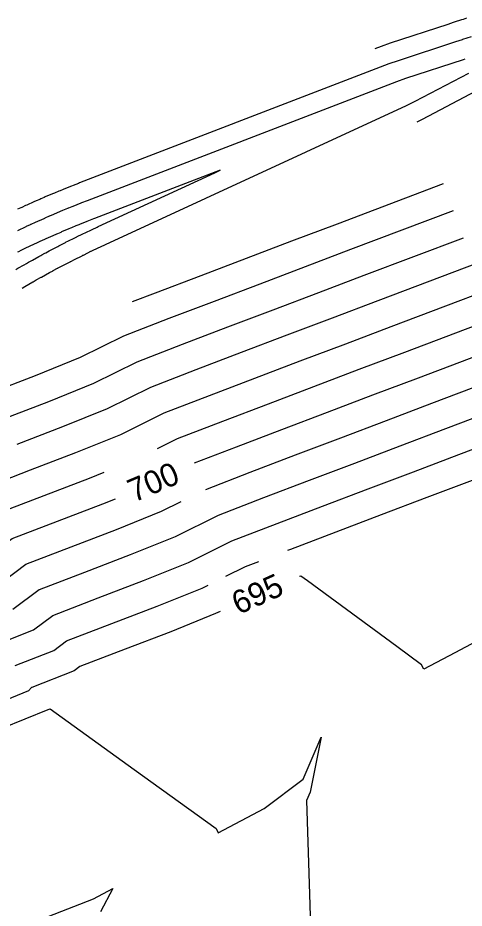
# Model space of a CAD drawing. Extents: x 1487507 to 1489130, y 497211 to 499439.
# Drawn here: x 1488002.7 to 1488049, y 498507 to 498599.3 of the extents above; entities that cross this region are included whole.
import ezdxf

# ---------------------------------------------------------------- set-up
doc = ezdxf.new("R2010")
doc.units = 0
for name, color, linetype in [('Prop CMT Ditch DDE', 7, 'Continuous'), ('Prop Drainage Ditch Flow Line', 7, 'Continuous'), ('Prop Drainage Structure Pipe Outlet Channel Detail CELL', 7, 'Continuous')]:
    doc.layers.add(name, color=color, linetype=linetype)

msp = doc.modelspace()

# ---------------------------------------------------------------- linework, layer by layer
at = {"layer": 'Prop CMT Ditch DDE'}
for points in [[(1488039.747, 498596.07), (1488040.392, 498596.318), (1488041.336, 498596.654), (1488047.303, 498598.602), (1488047.879, 498598.79), (1488047.981, 498598.823), (1488048.73, 498599.075), (1488048.888, 498599.128), (1488049.261, 498599.256)], [(1488049.698, 498597.299), (1488048.812, 498597), (1488048.773, 498596.987), (1488048.745, 498596.977), (1488048.081, 498596.76), (1488042.114, 498594.811), (1488041.17, 498594.476), (1488009.111, 498582.152), (1488008.992, 498582.105), (1488008.457, 498581.897), (1488008.267, 498581.821), (1488007.486, 498581.509), (1488007.402, 498581.475), (1488007.101, 498581.352), (1488006.97, 498581.298), (1488006.519, 498581.111), (1488006.294, 498581.016), (1488005.556, 498580.704), (1488005.445, 498580.656), (1488005.106, 498580.51), (1488004.981, 498580.455), (1488004.596, 498580.286), (1488004.365, 498580.183), (1488003.64, 498579.859), (1488003.517, 498579.803), (1488003.128, 498579.626), (1488003.024, 498579.578), (1488002.689, 498579.423)], [(1488049.04, 498594.977), (1488048.859, 498594.917), (1488042.892, 498592.969), (1488041.949, 498592.633), (1488009.889, 498580.309), (1488009.321, 498580.088), (1488009.248, 498580.06), (1488008.393, 498579.719), (1488008.295, 498579.68), (1488007.954, 498579.541), (1488007.917, 498579.526), (1488007.862, 498579.503), (1488007.346, 498579.29), (1488006.476, 498578.923), (1488006.401, 498578.891), (1488005.993, 498578.715), (1488005.96, 498578.701), (1488005.493, 498578.497), (1488005.459, 498578.482), (1488005.397, 498578.454), (1488004.522, 498578.064), (1488004.045, 498577.847), (1488004.019, 498577.835), (1488003.998, 498577.825), (1488003.588, 498577.636), (1488003.547, 498577.617), (1488002.658, 498577.199)], [(1488003.162, 498571.258), (1488003.448, 498571.427), (1488004.271, 498571.903), (1488004.29, 498571.914), (1488004.298, 498571.919), (1488004.623, 498572.104), (1488005.119, 498572.383), (1488005.137, 498572.393), (1488005.168, 498572.41), (1488005.99, 498572.864), (1488006.365, 498573.068), (1488006.386, 498573.079), (1488006.82, 498573.312), (1488006.847, 498573.327), (1488006.898, 498573.354), (1488007.709, 498573.781), (1488008.134, 498574.001), (1488008.17, 498574.019), (1488008.201, 498574.035), (1488008.576, 498574.226), (1488009.365, 498574.622), (1488009.447, 498574.663), (1488009.498, 498574.688), (1488009.974, 498574.922), (1488010.286, 498575.073), (1488010.324, 498575.091), (1488011.101, 498575.462), (1488011.204, 498575.511), (1488011.275, 498575.544), (1488011.798, 498575.788), (1488042.988, 498590.173), (1488043.886, 498590.615), (1488049.443, 498593.533)], [(1488044.08, 498588.486), (1488044.664, 498588.773), (1488050.221, 498591.691)], [(1488087.147, 498587.769), (1488040.009, 498569.944), (1488035.296, 498568.161), (1488030.584, 498566.375), (1488025.873, 498564.587), (1488021.163, 498562.797), (1488016.465, 498560.986), (1488011.983, 498558.766), (1488007.322, 498556.883), (1488002.617, 498555.084)], [(1488017.17, 498554.642), (1488019.272, 498555.683), (1488023.971, 498557.494), (1488028.68, 498559.284), (1488033.391, 498561.072), (1488038.103, 498562.858), (1488042.817, 498564.641), (1488089.955, 498582.465), (1488091.211, 498582.934), (1488094.526, 498584.179), (1488095.693, 498584.618), (1488099.077, 498585.901), (1488100.17, 498586.256)], [(1487999.317, 498550.632), (1488004.02, 498552.433), (1488008.725, 498554.232), (1488013.386, 498556.114), (1488017.868, 498558.334), (1488022.567, 498560.146), (1488027.277, 498561.936), (1488031.988, 498563.724), (1488036.7, 498565.509), (1488041.413, 498567.293), (1488088.551, 498585.117)], [(1488046.785, 498582.054), (1488035.798, 498577.9), (1488031.085, 498576.116), (1488026.373, 498574.33), (1488021.662, 498572.542), (1488016.952, 498570.752), (1488014.566, 498569.832)], [(1488022.193, 498550.423), (1488026.778, 498552.191), (1488031.488, 498553.981), (1488036.199, 498555.769), (1488040.911, 498557.554), (1488045.624, 498559.338), (1488092.762, 498577.162), (1488093.195, 498577.323), (1488097.349, 498578.884), (1488097.695, 498579.014), (1488097.794, 498579.052)], [(1488001.213, 498557.736), (1488005.918, 498559.535), (1488010.579, 498561.418), (1488015.061, 498563.638), (1488019.76, 498565.449), (1488024.469, 498567.239), (1488029.18, 498569.027), (1488033.892, 498570.813), (1488038.605, 498572.596), (1488048.891, 498576.485)], [(1488094.166, 498574.51), (1488047.028, 498556.686), (1488042.314, 498554.903), (1488037.602, 498553.117), (1488032.891, 498551.329), (1488028.182, 498549.539), (1488023.483, 498547.727), (1488019.001, 498545.507), (1488014.34, 498543.625), (1488009.635, 498541.826), (1488004.931, 498540.025), (1488002.199, 498537.977)], [(1488000.749, 498534.455), (1488004.32, 498535.863), (1488006.335, 498537.373), (1488011.039, 498539.174), (1488015.744, 498540.973), (1488020.405, 498542.856), (1488024.887, 498545.076), (1488029.585, 498546.887), (1488034.295, 498548.677), (1488039.006, 498550.465), (1488043.718, 498552.251), (1488048.431, 498554.034), (1488074.272, 498563.806)], [(1487940.538, 498514.989), (1487953.072, 498520.432), (1487957.673, 498522.429), (1487962.274, 498524.424), (1487966.876, 498526.418), (1487971.478, 498528.41), (1487972.399, 498528.808), (1487973.558, 498529.31), (1487975.712, 498531.1), (1487977.261, 498531.763), (1487979.821, 498534.024), (1487981.476, 498534.703), (1487983.912, 498536.984), (1487985.699, 498537.574), (1487988.117, 498539.726), (1487989.914, 498540.428), (1487991.762, 498541.175), (1487993.944, 498543.574), (1487993.948, 498543.575), (1487995.835, 498544.319), (1488000.72, 498547.98), (1488005.424, 498549.781), (1488010.129, 498551.58), (1488011.661, 498552.199)], [(1488030.681, 498544.117), (1488030.989, 498544.235), (1488035.699, 498546.026), (1488040.41, 498547.813), (1488045.122, 498549.599), (1488049.835, 498551.383), (1488053.23, 498552.667), (1488065.671, 498543.413), (1488065.905, 498542.971), (1488076.427, 498548.539), (1488074.837, 498545.435), (1488076.107, 498515.557), (1488085.882, 498508.286), (1488089.343, 498507.855), (1488078.822, 498502.285), (1488079.056, 498501.843), (1488079.318, 498495.687), (1488079.802, 498484.086), (1488080.156, 498475.271), (1488079.175, 498474.583), (1488075.048, 498471.692), (1488070.92, 498468.804), (1488066.79, 498465.918), (1488066.142, 498465.465)], [(1488000.077, 498540.091), (1488003.528, 498542.677), (1488008.232, 498544.478), (1488012.937, 498546.277), (1488017.597, 498548.159), (1488019.652, 498549.177)], [(1488024.27, 498541.423), (1488026.291, 498542.424), (1488027.684, 498542.961)], [(1488002.449, 498532.175), (1488006.441, 498533.749), (1488007.739, 498534.721), (1488012.443, 498536.523), (1488017.148, 498538.322), (1488021.809, 498540.204), (1488022.433, 498540.513)], [(1488001.101, 498525.694), (1488005.837, 498527.608), (1488005.84, 498527.611), (1488006.071, 498527.702), (1488014.776, 498521.428), (1488023.251, 498515.3), (1488023.485, 498514.858), (1488028.237, 498517.373), (1488032.278, 498520.426), (1488034.156, 498524.774), (1488032.999, 498519.064), (1488032.624, 498518.213), (1488032.938, 498508.493), (1488033.285, 498497.149)], [(1488005.863, 498506.204), (1488010.561, 498508.016), (1488012.559, 498509.073), (1488011.271, 498506.675)]]:
    msp.add_lwpolyline(points, dxfattribs=at)
at = {"layer": 'Prop Drainage Ditch Flow Line'}
for points in [[(1488002.496, 498573.185), (1488002.724, 498573.318), (1488003.355, 498573.682), (1488003.609, 498573.826), (1488003.695, 498573.875), (1488003.827, 498573.95), (1488004.22, 498574.171), (1488004.884, 498574.537), (1488005.09, 498574.651), (1488005.185, 498574.702), (1488005.495, 498574.87), (1488005.602, 498574.927), (1488005.966, 498575.122), (1488006.657, 498575.486), (1488006.846, 498575.585), (1488006.945, 498575.636), (1488007.316, 498575.828), (1488007.647, 498575.996), (1488007.731, 498576.039), (1488007.907, 498576.127), (1488008.62, 498576.484), (1488009.06, 498576.7), (1488009.158, 498576.748), (1488009.223, 498576.779), (1488009.515, 498576.921), (1488009.672, 498576.996), (1488010.414, 498577.348), (1488010.923, 498577.585), (1488011.02, 498577.631), (1488023.13, 498583.216), (1488023.676, 498583.468), (1488010.667, 498578.467), (1488010.562, 498578.426), (1488010.038, 498578.222), (1488009.874, 498578.157), (1488009.104, 498577.85), (1488009.035, 498577.822), (1488008.733, 498577.7), (1488008.283, 498577.514), (1488008.173, 498577.469), (1488007.988, 498577.391), (1488007.246, 498577.078), (1488007.155, 498577.039), (1488006.814, 498576.892), (1488006.707, 498576.846), (1488006.323, 498576.678), (1488005.615, 498576.363), (1488005.403, 498576.269), (1488005.287, 498576.216), (1488004.91, 498576.045), (1488004.59, 498575.897), (1488004.487, 498575.85), (1488003.806, 498575.53), (1488003.575, 498575.422), (1488003.433, 498575.353), (1488003.024, 498575.157), (1488002.762, 498575.031), (1488002.667, 498574.984)], [(1488021.028, 498553.167), (1488025.374, 498554.842), (1488030.084, 498556.632), (1488034.795, 498558.42), (1488039.507, 498560.206), (1488044.22, 498561.989), (1488091.358, 498579.814), (1488092.203, 498580.128), (1488095.938, 498581.532), (1488096.694, 498581.816), (1488096.772, 498581.845)], [(1488047.838, 498579.27), (1488037.202, 498575.248), (1488032.489, 498573.464), (1488027.776, 498571.679), (1488023.066, 498569.891), (1488018.356, 498568.101), (1488013.657, 498566.289), (1488009.175, 498564.069), (1488004.514, 498562.187), (1487999.809, 498560.388), (1487995.105, 498558.587), (1487987.349, 498552.775), (1487987.146, 498552.695), (1487983.719, 498548.928), (1487983.521, 498548.848), (1487983.328, 498548.773), (1487979.609, 498545.463), (1487979.451, 498545.41), (1487975.764, 498541.959), (1487975.646, 498541.911), (1487971.808, 498538.52), (1487971.788, 498538.511), (1487971.225, 498538.043)], [(1487941.332, 498513.16), (1487954.008, 498518.664), (1487958.608, 498520.661), (1487963.209, 498522.656), (1487967.811, 498524.65), (1487972.414, 498526.642), (1487973.335, 498527.041), (1487974.802, 498527.675), (1487976.692, 498529.247), (1487978.624, 498530.073), (1487980.865, 498532.053), (1487982.904, 498532.889), (1487985.027, 498534.877), (1487987.222, 498535.602), (1487989.314, 498537.465), (1487991.512, 498538.323), (1487993.773, 498539.237), (1487995.644, 498541.293), (1487995.648, 498541.295), (1487997.956, 498542.205), (1488002.124, 498545.328), (1488006.828, 498547.129), (1488011.533, 498548.928), (1488012.828, 498549.451)], [(1488065.029, 498494.984), (1488068.27, 498496.7), (1488067.412, 498496.804), (1488064.786, 498497.119), (1488059.539, 498500.99), (1488054.956, 498504.361), (1488054.745, 498510.046), (1488054.3, 498521.574), (1488053.836, 498533.138), (1488053.787, 498534.292), (1488055.382, 498537.399), (1488052.412, 498535.827), (1488047.993, 498533.488), (1488044.796, 498531.797), (1488044.563, 498532.239), (1488041.994, 498534.134), (1488032.73, 498540.946), (1488032.031, 498541.444), (1488031.906, 498541.396)], [(1488023.666, 498537.777), (1488023.212, 498537.552), (1488018.551, 498535.67), (1488013.846, 498533.871), (1488009.142, 498532.07), (1488008.563, 498531.636), (1488004.15, 498529.895), (1488004.141, 498529.892), (1488003.827, 498529.546), (1487999.503, 498527.799)]]:
    msp.add_lwpolyline(points, dxfattribs=at)

# ---------------------------------------------------------------- texts
at = {"layer": 'Prop Drainage Structure Pipe Outlet Channel Detail CELL'}
for s, rotation, p in [('700', 23.01214, (1488014.74, 498549.046)), ('695', 24.25183, (1488025.576, 498537.405))]:
    msp.add_text(s, height=2.4, rotation=rotation, dxfattribs=at).set_placement(p)

doc.saveas('drawing.dxf')
